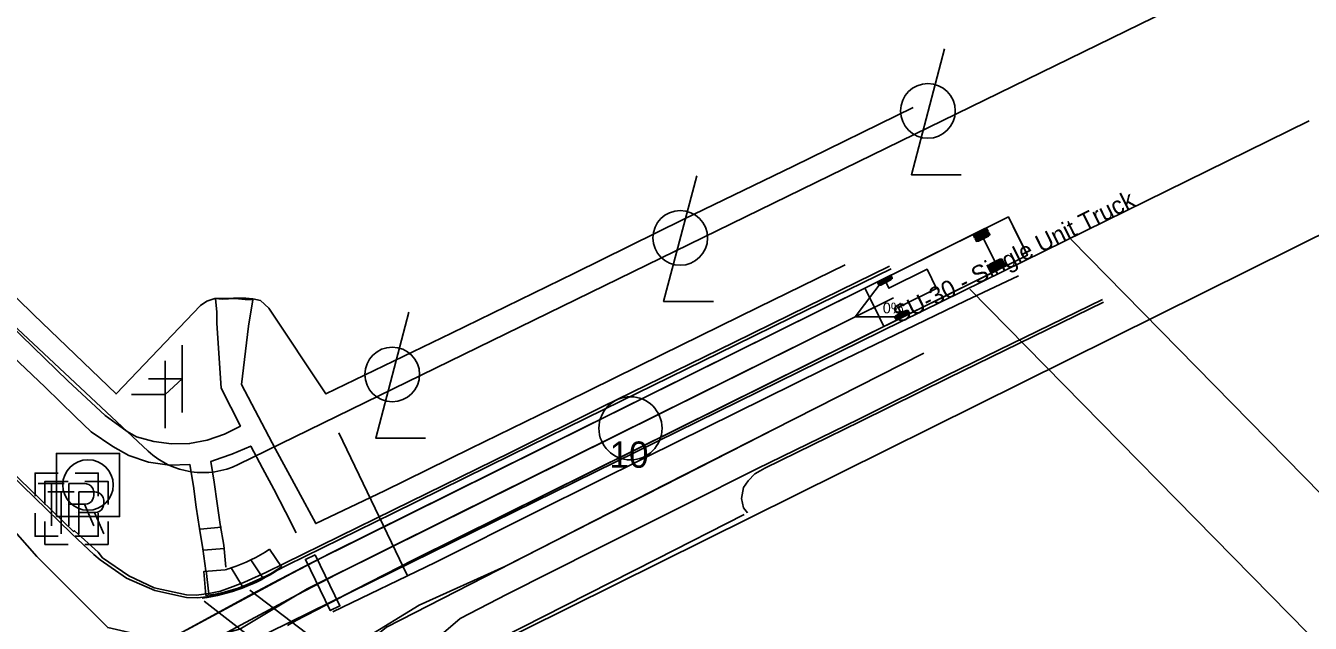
# Model space of a CAD drawing. Extents: x 1475900 to 1484331, y 375914 to 383395.
# Drawn here: x 1479629.9 to 1479870.3, y 379936.7 to 380048.5 of the extents above; entities that cross this region are included whole.
import ezdxf

# ---------------------------------------------------------------- set-up
doc = ezdxf.new("R2010")
doc.units = 0
for name, color, linetype in [('Default', 7, 'Continuous'), ('LT_X_Poles', 7, 'Continuous'), ('PM_X_CL_Double_Solid', 7, 'Continuous'), ('PM_X_Crosswalk', 7, 'Continuous'), ('PM_X_Misc', 7, 'Continuous'), ('PM_X_Stop_Line', 7, 'Continuous'), ('PV_X_Curb', 7, 'Continuous'), ('PV_X_Walk', 7, 'Continuous'), ('RW_X_CL_20', 7, 'Continuous'), ('RW_X_Esmt_SH', 7, 'Continuous'), ('RW_X_Esmt_U', 7, 'Continuous'), ('RW_X_Text', 7, 'Continuous'), ('SG_X_Poles', 7, 'Continuous'), ('SG_X_PullBox', 7, 'Continuous'), ('SG_X_PullBox (Construction)', 7, 'Continuous'), ('SN_X_Public', 7, 'Continuous')]:
    doc.layers.add(name, color=color, linetype=linetype)

# ---------------------------------------------------------------- blocks, each defined once
blk = doc.blocks.new('SPOLE')
at = {"layer": 'SG_X_Poles'}
blk.add_lwpolyline([(-0.01905, -0.01905), (0.01905, -0.01905), (0.01905, 0.01905), (-0.01905, 0.01905)], close=True, dxfattribs=at)
blk.add_circle((0, 0), 0.01524, dxfattribs=at)
blk = doc.blocks.new('LPOLE')
at = {"layer": 'LT_X_Poles'}
blk.add_lwpolyline([(0.00999, 0.03751), (-0.01001, -0.0385), (0.02, -0.0385)], dxfattribs=at)
blk.add_circle((0, 0), 0.01651, dxfattribs=at)
blk = doc.blocks.new('SGN1P')
at = {"layer": 'SN_X_Public'}
for p, q in [((0, 0.02032), (0, -0.02032)), ((0, 0), (-0.02032, 0))]:
    blk.add_line(p, q, dxfattribs=at)
blk = doc.blocks.new('POINT_DISPLAY')
at = {"layer": 'Default'}
blk.add_line((0, 0), (0, 0), dxfattribs=at)
blk = doc.blocks.new('SIGPB')
at = {"layer": 'SG_X_PullBox'}
for p, q in [((-0.01722, 0.0127), (-0.00142, 0.0127)), ((-0.00922, 0.0127), (-0.00922, -0.0127)), ((0.01082, 0.0003), (0.01642, -0.0127))]:
    blk.add_line(p, q, dxfattribs=at)
for points in [[(-0.00508, 0.01905), (-0.01905, 0.01905), (-0.01905, 0.00508)], [(0.01905, 0.00508), (0.01905, 0.01905), (0.00508, 0.01905)], [(0.00142, -0.0127), (0.00142, 0.0127), (0.01102, 0.0127), (0.01202, 0.0125), (0.01342, 0.0121), (0.01402, 0.0117), (0.01462, 0.0113), (0.01542, 0.0103), (0.01602, 0.0093), (0.01642, 0.0077), (0.01642, 0.0053), (0.01622, 0.0045), (0.01582, 0.0033), (0.01502, 0.0019), (0.01422, 0.0013), (0.01362, 0.0009), (0.01322, 0.0007), (0.01262, 0.0005), (0.01082, 0.0003), (0.00142, 0.0003)], [(-0.01905, -0.00508), (-0.01905, -0.01905), (-0.00508, -0.01905)], [(0.00508, -0.01905), (0.01905, -0.01905), (0.01905, -0.00508)]]:
    blk.add_lwpolyline(points, dxfattribs=at)
at = {"layer": 'SG_X_PullBox (Construction)'}
blk.add_blockref('POINT_DISPLAY', (0, 0), dxfattribs=at)

msp = doc.modelspace()

# ---------------------------------------------------------------- linework, layer by layer
at = {"layer": 'Default'}
for p, q in [((1479659.17, 379982.42), (1479655.97, 379979.46)), ((1479688.47, 379972.29), (1479701.35, 379945.55))]:
    msp.add_line(p, q, dxfattribs=at)
at = {"layer": 'PM_X_CL_Double_Solid'}
msp.add_lwpolyline([(1479687.38, 379938.81), (1479706.5, 379948.02), (1479725.91, 379957.78), (1479746.01, 379967.72), (1479779.43, 379984.27), (1479805.77, 379996.99), (1479815.71, 380001.7)], dxfattribs=at)
at = {"layer": 'PM_X_Crosswalk'}
for p, q in [((1479663.29, 379940.79), (1479694.65, 379916.51)), ((1479696.98, 379923.76), (1479671.85, 379942.85))]:
    msp.add_line(p, q, dxfattribs=at)
at = {"layer": 'PM_X_Misc'}
for points in [[(1479656.52, 379933.59), (1479672.44, 379942.2), (1479676.06, 379944.15), (1479683.35, 379947.97), (1479813.83, 380012.7), (1479817.38, 380005.54), (1479702.61, 379948.58), (1479697.1, 379945.79), (1479691.63, 379942.98), (1479685.49, 379939.78), (1479680.73, 379937.28), (1479679.39, 379936.53)], [(1479807.46, 380008.88), (1479809.97, 380010.12), (1479809.88, 380010.3), (1479807.38, 380009.05), (1479807.29, 380009.23), (1479809.8, 380010.48), (1479809.77, 380010.54), (1479809.39, 380010.5), (1479807.51, 380009.57), (1479807.26, 380009.29), (1479807.49, 380008.82), (1479807.87, 380008.85), (1479809.75, 380009.79), (1479810, 380010.06), (1479809.77, 380010.54)], [(1479660.06, 379935.45), (1479679.63, 379945.95), (1479686.93, 379949.75), (1479808.45, 380010.04), (1479812.01, 380002.87), (1479702.56, 379948.55), (1479696.73, 379945.6), (1479690.91, 379942.61), (1479684.38, 379939.2), (1479680.14, 379936.96), (1479678.86, 379936.24)], [(1479807.82, 380008.16), (1479810.33, 380009.4), (1479810.24, 380009.58), (1479807.73, 380008.34), (1479807.64, 380008.52), (1479810.15, 380009.76), (1479810.12, 380009.82), (1479809.75, 380009.79), (1479807.87, 380008.85), (1479807.61, 380008.58), (1479807.85, 380008.1), (1479808.22, 380008.14), (1479810.1, 380009.07), (1479810.36, 380009.34), (1479810.12, 380009.82)], [(1479810.31, 380003.14), (1479812.82, 380004.39), (1479812.73, 380004.57), (1479810.22, 380003.32), (1479810.13, 380003.5), (1479812.64, 380004.75), (1479812.61, 380004.8), (1479812.24, 380004.77), (1479810.36, 380003.84), (1479810.1, 380003.56), (1479810.34, 380003.08), (1479810.71, 380003.12), (1479812.59, 380004.05), (1479812.85, 380004.33), (1479812.61, 380004.8)], [(1479810.66, 380002.43), (1479813.17, 380003.67), (1479813.08, 380003.85), (1479810.58, 380002.6), (1479810.49, 380002.78), (1479812.99, 380004.03), (1479812.97, 380004.09), (1479812.59, 380004.05), (1479810.71, 380003.12), (1479810.46, 380002.84), (1479810.69, 380002.37), (1479811.07, 380002.4), (1479812.95, 380003.34), (1479813.2, 380003.61), (1479812.97, 380004.09)], [(1479789.55, 379999.99), (1479792.06, 380001.23), (1479791.97, 380001.41), (1479789.46, 380000.17), (1479789.37, 380000.35), (1479791.88, 380001.59), (1479791.85, 380001.65), (1479791.48, 380001.61), (1479789.6, 380000.68), (1479789.34, 380000.41), (1479789.58, 379999.93), (1479789.95, 379999.96), (1479791.83, 380000.9), (1479792.09, 380001.17), (1479791.85, 380001.65)], [(1479792.75, 379993.54), (1479795.26, 379994.78), (1479795.17, 379994.96), (1479792.66, 379993.72), (1479792.57, 379993.9), (1479795.08, 379995.14), (1479795.05, 379995.2), (1479794.68, 379995.16), (1479792.79, 379994.23), (1479792.54, 379993.96), (1479792.78, 379993.48), (1479793.15, 379993.51), (1479795.03, 379994.45), (1479795.29, 379994.72), (1479795.05, 379995.2)]]:
    msp.add_lwpolyline(points, dxfattribs=at)
for points in [[(1479786.95, 379999.37), (1479813.83, 380012.7), (1479815.6, 380009.12), (1479817.38, 380005.54), (1479790.51, 379992.2), (1479788.73, 379995.79)], [(1479799.48, 380001.12), (1479800.37, 379999.33), (1479793.2, 379995.77), (1479794.09, 379993.98), (1479785.15, 379994.01), (1479790.54, 380001.15), (1479791.42, 379999.36), (1479798.59, 380002.91)]]:
    msp.add_lwpolyline(points, close=True, dxfattribs=at)
msp.add_circle((1479743.08, 379973.14), 5.91, dxfattribs=at)
at = {"layer": 'PM_X_Stop_Line'}
msp.add_lwpolyline([(1479684.05, 379949.47), (1479682.25, 379948.6), (1479686.9, 379939.03), (1479688.7, 379939.9)], close=True, dxfattribs=at)
at = {"layer": 'PV_X_Curb'}
msp.add_line((1479670.47, 379943.52), (1479668.33, 379947.01), dxfattribs=at)
for points in [[(1479795.99, 380033.19), (1479773.61, 380022.19), (1479753.08, 380012.28), (1479732.58, 380002.19), (1479709.58, 379990.94), (1479686.04, 379979.57), (1479675.42, 379995.64), (1479673.84, 379997.04), (1479672.39, 379997.4), (1479671.07, 379997.48), (1479668.75, 379997.51), (1479666.58, 379997.44), (1479665.26, 379997.43), (1479663.76, 379996.91), (1479662.62, 379996.12), (1479646.81, 379979.59), (1479631.39, 379994.41), (1479612.95, 380012.39), (1479594.61, 380030.05), (1479574.05, 380049.98), (1479559.35, 380064.64), (1479550.33, 380073.36), (1479530.48, 380092.84), (1479523.35, 380099.69)], [(1479791.59, 380003.46), (1479772.98, 379994.38), (1479762.44, 379989.23), (1479737.89, 379977.23), (1479720.64, 379968.61), (1479698.71, 379957.88), (1479678.41, 379947.91), (1479674.82, 379946.16), (1479670.83, 379944.35), (1479668.74, 379943.53), (1479666.34, 379942.65), (1479664.18, 379942.2), (1479661.88, 379941.9), (1479660, 379941.97), (1479653.93, 379943.27), (1479649.18, 379945.53), (1479644.26, 379948.89), (1479643.43, 379949.99), (1479639.01, 379953.96), (1479638.82, 379953.85), (1479620.56, 379971.48)], [(1479791.85, 380002.99), (1479773.25, 379993.87), (1479762.77, 379988.77), (1479738.12, 379976.64), (1479720.84, 379968.21), (1479698.69, 379957.24), (1479678.81, 379947.54), (1479674.95, 379945.56), (1479671.19, 379943.85), (1479668.84, 379942.93), (1479666.48, 379942.24), (1479664.29, 379941.7), (1479662.03, 379941.4), (1479659.99, 379941.51), (1479654.02, 379942.77), (1479648.76, 379945.1), (1479643.81, 379948.55), (1479642.64, 379949.52), (1479640.65, 379951.39), (1479638.38, 379953.49), (1479620.03, 379971.27)], [(1479708.06, 379934.88), (1479711.18, 379937.55), (1479719.99, 379942.12), (1479736.74, 379950.53), (1479753.3, 379958.8), (1479766.72, 379965.56), (1479785.84, 379974.83), (1479802.25, 379983.05), (1479831.41, 379997.25)], [(1479764.96, 379957.31), (1479764.23, 379958.29), (1479763.83, 379960.02), (1479764.23, 379962.05), (1479765.13, 379963.34), (1479766.36, 379964.64), (1479767.37, 379965.19), (1479768.2, 379965.67), (1479786.07, 379974.44), (1479802.59, 379982.62), (1479831.64, 379996.73)], [(1479667.19, 379946.67), (1479663.21, 379946.33), (1479663.59, 379941.84)]]:
    msp.add_lwpolyline(points, dxfattribs=at)
for centre, radius, start, end in [((1479658.35, 379975.09), 34.05, 277.6794, 303.7534), ((1479659.1, 379975.09), 29.55, 285.8924, 288.1919), ((1479659.1, 379975.09), 33.55, 277.6794, 289.8035)]:
    msp.add_arc(centre, radius, start, end, dxfattribs=at)
at = {"layer": 'PV_X_Walk'}
for p, q in [((1479662.54, 379954.3), (1479666.52, 379954.64)), ((1479663.07, 379950.33), (1479667.06, 379950.67)), ((1479675.52, 379950.52), (1479677.74, 379947.19)), ((1479672.04, 379948.52), (1479674.28, 379945.17))]:
    msp.add_line(p, q, dxfattribs=at)
for points in [[(1479508.9, 380098.74), (1479528.42, 380079.59), (1479545.91, 380063.23), (1479563.42, 380046.67), (1479583.68, 380027.56), (1479601.43, 380010.98), (1479618.88, 379994.72), (1479633.51, 379980.86), (1479639.16, 379975.37), (1479642.14, 379972.51), (1479646.22, 379969.76), (1479649.18, 379968.04), (1479652.86, 379966.82), (1479656.79, 379966.27), (1479660.63, 379966.35), (1479661.26, 379962.34), (1479661.8, 379958.41), (1479662.4, 379954.37), (1479663.05, 379950.6), (1479663.59, 379946.45), (1479663.66, 379946.47), (1479664.16, 379942.19)], [(1479783.24, 380003.73), (1479767.07, 379995.8), (1479748.9, 379986.89), (1479731.06, 379978.1), (1479713.16, 379969.38), (1479697.03, 379961.47), (1479684.16, 379955.33), (1479680.85, 379961.43), (1479676.66, 379969.27), (1479670.26, 379981.37), (1479671.61, 379992.26), (1479672.42, 379997.21), (1479670.95, 379997.26), (1479669.11, 379997.42), (1479666.63, 379997.33), (1479665.43, 379997.46), (1479665.64, 379994.87), (1479665.66, 379992.85), (1479666.47, 379980.65), (1479670.08, 379973.56), (1479667.07, 379972.02), (1479663.84, 379970.93), (1479660.54, 379970.29), (1479657.16, 379970.23), (1479653.85, 379970.66), (1479650.6, 379971.56), (1479648.89, 379972.52), (1479644.74, 379975.56), (1479637.77, 379982.02), (1479624.64, 379994.68)], [(1479667.32, 379947.17), (1479666.94, 379951.26), (1479666.29, 379955.17), (1479665.72, 379959.06), (1479665.13, 379963.05), (1479664.56, 379966.95), (1479666.46, 379967.61), (1479668.44, 379968.32), (1479672.01, 379969.82), (1479674.22, 379965.71), (1479676.34, 379961.75), (1479678.51, 379957.53), (1479680.53, 379953.58)], [(1479764.35, 379957.04), (1479747.94, 379948.68), (1479730.88, 379939.97), (1479715, 379931.95)]]:
    msp.add_lwpolyline(points, dxfattribs=at)
for radius, start in [(29.55, 288.1919), (33.55, 289.8035)]:
    msp.add_arc((1479659.1, 379975.09), radius, start, 303.7534, dxfattribs=at)
at = {"layer": 'RW_X_CL_20'}
msp.add_line((1479642.33, 379918.73), (1479870.13, 380030.67), dxfattribs=at)
at = {"layer": 'RW_X_Esmt_SH'}
for p, q in [((1479669.64, 379966.37), (1479853.6, 380056.19)), ((1479607.65, 380011.05), (1479652.81, 379968.89)), ((1479687.35, 379917.68), (1479879.01, 380012.75))]:
    msp.add_line(p, q, dxfattribs=at)
msp.add_arc((1479663.06, 379979.85), 15, 226.9362, 296.0142, dxfattribs=at)
at = {"layer": 'RW_X_Esmt_U'}
for p, q in [((1479825.48, 380008.52), (1479965.05, 379866.47)), ((1479806.63, 379999.17), (1479951.46, 379851.77))]:
    msp.add_line(p, q, dxfattribs=at)
at = {"layer": 'RW_X_Text'}
for points in [[(1479498.76, 380054.27), (1479542.61, 380009.77), (1479579.04, 379974.72), (1479593.11, 379960.7), (1479603.72, 379949.15), (1479613.43, 379938.94), (1479630.83, 379922.33), (1479649.98, 379916.32), (1479663.12, 379916.63), (1479679.72, 379921.61), (1479697.44, 379935.96), (1479749.58, 379962.61), (1479797.99, 379987.23)], [(1479792.31, 379997.56), (1479710.02, 379956.74), (1479682.58, 379943.12), (1479669.95, 379935.54), (1479659.06, 379932.66), (1479645.23, 379935.86), (1479631.96, 379949.18), (1479613.32, 379970.31), (1479554.76, 380028.14)], [(1479792.31, 379997.56), (1479688.12, 379945.87), (1479680.71, 379942), (1479661.48, 379931.68), (1479658.87, 379928.92), (1479653.52, 379923.03), (1479651.72, 379914.38), (1479652.44, 379904.37), (1479656.24, 379892.75), (1479663.84, 379880.53), (1479675, 379870.68), (1479716.91, 379832.05), (1479737.94, 379812.66)], [(1479797.55, 379798.42), (1479779.29, 379815.04), (1479755.95, 379837.17), (1479710.6, 379878.47), (1479700.46, 379887.97), (1479695.14, 379892.26), (1479687.63, 379898.54), (1479684.65, 379909.71), (1479684.09, 379918.26), (1479685.98, 379925.49), (1479693.36, 379933.84), (1479703.54, 379940.07), (1479719.59, 379947.28), (1479755.69, 379965.71), (1479770.46, 379973.23)]]:
    msp.add_lwpolyline(points, dxfattribs=at)

# ---------------------------------------------------------------- block references
at = {"layer": 'LT_X_Poles', "xscale": 310.00000000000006, "yscale": 310.00000000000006}
for p in [(1479798.76, 380032.54), (1479752.39, 380008.78), (1479698.5, 379983.22)]:
    msp.add_blockref('LPOLE', p, dxfattribs=at)
at = {"layer": 'SG_X_Poles', "xscale": 310.00000000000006, "yscale": 310.00000000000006}
msp.add_blockref('SPOLE', (1479641.54, 379962.54), dxfattribs=at)
at = {"layer": 'SG_X_PullBox', "xscale": 310.00000000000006, "yscale": 310.00000000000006}
for p in [(1479637.54, 379958.86), (1479639.39, 379957.31)]:
    msp.add_blockref('SIGPB', p, dxfattribs=at)
at = {"layer": 'SN_X_Public', "xscale": 310.00000000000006, "yscale": 310.00000000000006}
for p in [(1479659.17, 379982.42), (1479655.97, 379979.46)]:
    msp.add_blockref('SGN1P', p, dxfattribs=at)

# ---------------------------------------------------------------- texts
at = {"layer": 'PM_X_Misc'}
msp.add_text('SU-30 - Single Unit Truck', height=3.2808, rotation=26.3866, dxfattribs=at).set_placement((1479793.26, 379992.72))
for s, height, p in [('0%', 2, (1479790.31, 379994.66)), ('10', 4.921, (1479739.15, 379965.76))]:
    msp.add_text(s, height=height, dxfattribs=at).set_placement(p)

doc.saveas('drawing.dxf')
